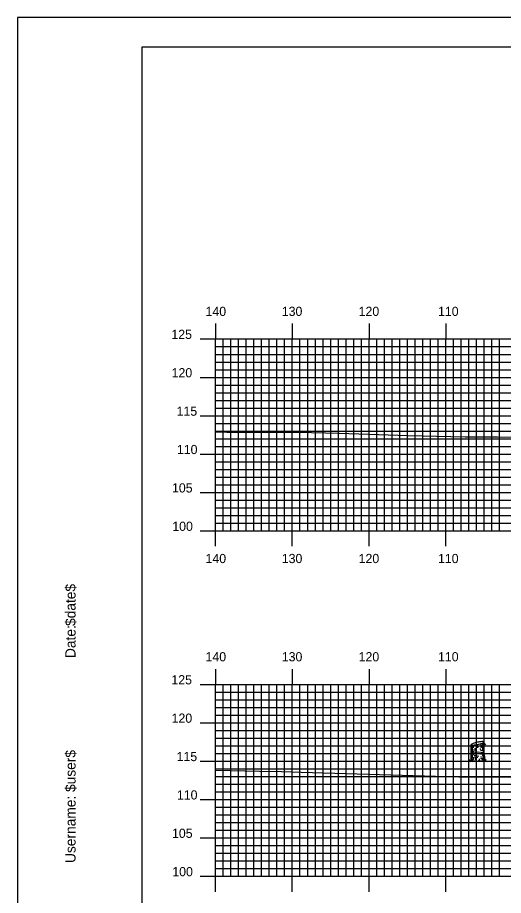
# Model space of a CAD drawing. Extents: x 1772809 to 1773153, y 442591 to 442811.
# Drawn here: x 1772809.3 to 1772872.6, y 442696.2 to 442810.5 of the extents above; entities that cross this region are included whole.
import ezdxf

# ---------------------------------------------------------------- set-up
doc = ezdxf.new("R2010")
doc.units = 0
for name, color, linetype in [('BORDER', 7, 'Continuous'), ('H_V ANNOTATION', 7, 'Continuous'), ('M_Trees_Conifer_Pay', 7, 'Continuous'), ('MAJOR', 7, 'Continuous'), ('MINOR', 7, 'Continuous'), ('PLOT BOUNDARY', 7, 'Continuous'), ('S_Roadway_Centerline', 7, 'Continuous')]:
    doc.layers.add(name, color=color, linetype=linetype)

msp = doc.modelspace()

# ---------------------------------------------------------------- linework, layer by layer
at = {"layer": 'BORDER'}
msp.add_lwpolyline([(1772825.52, 442596.67), (1773145.52, 442596.67), (1773145.52, 442806.67), (1772825.52, 442806.67)], close=True, dxfattribs=at)
at = {"layer": 'M_Trees_Conifer_Pay'}
for p, q in [((1772870.1, 442714.51), (1772870.1, 442716.16)), ((1772868.43, 442714.1), (1772868.43, 442715.82)), ((1772868.48, 442715.78), (1772868.48, 442715.31)), ((1772868.48, 442715.25), (1772868.48, 442714.94)), ((1772868.54, 442715.77), (1772868.54, 442715.68)), ((1772868.54, 442715.6), (1772868.54, 442715.4)), ((1772868.54, 442715.34), (1772868.54, 442715.14)), ((1772868.54, 442715.09), (1772868.54, 442714.76)), ((1772868.66, 442715.77), (1772868.66, 442715.53)), ((1772868.66, 442715.49), (1772868.66, 442715.42)), ((1772868.66, 442715.01), (1772868.66, 442714.88)), ((1772868.88, 442715.79), (1772868.88, 442715.62)), ((1772868.88, 442715.38), (1772868.88, 442715.14)), ((1772869.29, 442715.55), (1772869.29, 442715.46)), ((1772869.68, 442715.83), (1772869.68, 442715.63)), ((1772869.68, 442715.57), (1772869.68, 442715.48)), ((1772869.68, 442715.13), (1772869.68, 442715.03)), ((1772869.91, 442716.02), (1772869.91, 442715.8)), ((1772869.91, 442715.71), (1772869.91, 442715.66)), ((1772869.96, 442715.53), (1772869.91, 442715.47)), ((1772869.91, 442715.33), (1772869.91, 442715.2)), ((1772869.91, 442715.09), (1772869.91, 442714.98)), ((1772870.02, 442716.08), (1772870.02, 442715.92)), ((1772870.02, 442715.85), (1772870.02, 442715.73)), ((1772870.02, 442715.54), (1772870.02, 442715.2)), ((1772870.02, 442715.17), (1772870.02, 442715)), ((1772868.48, 442714.89), (1772868.48, 442714.4)), ((1772868.48, 442714.35), (1772868.48, 442714.1)), ((1772868.54, 442714.7), (1772868.54, 442714.57)), ((1772868.54, 442714.47), (1772868.54, 442714.09)), ((1772868.66, 442714.6), (1772868.66, 442714.46)), ((1772868.66, 442714.2), (1772868.66, 442714.11)), ((1772868.88, 442714.9), (1772868.88, 442714.75)), ((1772868.88, 442714.7), (1772868.88, 442714.53)), ((1772868.88, 442714.25), (1772868.88, 442714.1)), ((1772869.29, 442714.94), (1772869.29, 442714.87)), ((1772869.29, 442714.84), (1772869.29, 442714.69)), ((1772869.29, 442714.4), (1772869.29, 442714.25)), ((1772869.68, 442714.66), (1772869.68, 442714.52)), ((1772869.68, 442714.28), (1772869.68, 442714.2)), ((1772869.91, 442714.84), (1772869.91, 442714.7)), ((1772869.91, 442714.47), (1772869.91, 442714.3)), ((1772870.02, 442714.96), (1772870.02, 442714.74)), ((1772870.02, 442714.71), (1772870.02, 442714.64)), ((1772870.02, 442714.59), (1772870.02, 442714.42)), ((1772868.66, 442713.71), (1772868.83, 442713.77)), ((1772869.1, 442713.64), (1772868.97, 442713.71))]:
    msp.add_line(p, q, dxfattribs=at)
for points in [[(1772868.61, 442715.13), (1772868.61, 442715.22), (1772868.65, 442715.2), (1772868.65, 442715.11)], [(1772869.88, 442715.62), (1772869.85, 442715.53), (1772869.84, 442715.47), (1772869.88, 442715.4)], [(1772869.91, 442715.66), (1772869.95, 442715.58), (1772870, 442715.64), (1772870.05, 442715.71), (1772870.15, 442715.9), (1772870.21, 442715.95), (1772870.24, 442715.95)], [(1772869.93, 442715.4), (1772869.96, 442715.53), (1772870.03, 442715.64), (1772870.06, 442715.71), (1772870.13, 442715.86)], [(1772870.14, 442715.89), (1772870.22, 442715.9), (1772870.29, 442715.8)], [(1772870.1, 442714.51), (1772870.15, 442714.25), (1772870.16, 442713.97), (1772870.22, 442713.85), (1772870.36, 442713.82), (1772870.13, 442713.78), (1772870.13, 442713.78), (1772870.13, 442713.73), (1772870.38, 442713.64), (1772870.11, 442713.66), (1772869.75, 442713.68), (1772869.43, 442713.67), (1772869.44, 442713.75), (1772869.29, 442713.67), (1772869.1, 442713.64), (1772869.12, 442713.58), (1772868.86, 442713.62), (1772868.64, 442713.59), (1772868.34, 442713.61), (1772868.63, 442713.67), (1772868.66, 442713.71), (1772868.5, 442713.76), (1772868.26, 442713.78), (1772868.02, 442713.78), (1772868.36, 442713.83), (1772868.41, 442713.91), (1772868.43, 442714.1)], [(1772868.48, 442714.05), (1772868.46, 442713.97), (1772868.44, 442713.88)], [(1772868.56, 442714.03), (1772868.56, 442713.92), (1772868.51, 442713.83), (1772868.5, 442713.76)], [(1772868.72, 442714.06), (1772868.72, 442713.93), (1772868.63, 442713.83)], [(1772868.95, 442713.82), (1772869.01, 442713.91), (1772869.04, 442714.05)], [(1772869.44, 442713.75), (1772869.51, 442713.89), (1772869.52, 442713.99)], [(1772869.69, 442714.12), (1772869.7, 442713.99), (1772869.77, 442713.95)], [(1772869.75, 442714.73), (1772869.76, 442714.65), (1772869.81, 442714.66), (1772869.8, 442714.83)], [(1772869.96, 442713.73), (1772869.95, 442713.87), (1772869.88, 442714)], [(1772869.92, 442714.22), (1772870, 442714.12), (1772870, 442713.94), (1772870.13, 442713.78)], [(1772870.02, 442714.37), (1772870.03, 442714.22), (1772870.08, 442714.15), (1772870.09, 442713.95)]]:
    msp.add_lwpolyline(points, dxfattribs=at)
for centre, radius, start, end in [((1772870.29, 442711.05), 5.18, 95.3794, 101.7194), ((1772869.88, 442715.41), 0.802, 79.2194, 95.3794), ((1772869.98, 442715.95), 0.251, 71.0501, 79.2194), ((1772870.04, 442716.11), 0.0817, 56.7194, 71.0501), ((1772870.05, 442716.14), 0.0527, 46.923, 56.7194), ((1772870.07, 442716.15), 0.0314, 34.2194, 46.923), ((1772870.07, 442716.16), 0.0226, 11.7194, 23.4074), ((1772870.07, 442716.16), 0.0264, 23.4074, 34.2194), ((1772870.06, 442716.16), 0.0314, 336.5158, 349.2194), ((1772870.07, 442716.16), 0.0264, 349.2194, 0.0315), ((1772870.07, 442716.16), 0.0226, 0.0315, 11.7194), ((1772868.48, 442715.81), 0.0527, 146.7194, 156.5158), ((1772868.46, 442715.82), 0.0314, 156.5158, 169.2194), ((1772868.46, 442715.82), 0.0264, 169.2194, 180.0315), ((1772868.45, 442715.82), 0.0226, 180.0315, 191.7194), ((1772868.45, 442715.82), 0.0226, 191.7194, 203.4074), ((1772868.46, 442715.82), 0.0264, 203.4074, 214.2194), ((1772868.46, 442715.64), 0.0334, 163.9485, 180), ((1772868.46, 442715.64), 0.0334, 180, 196.0515), ((1772868.47, 442715.65), 0.0441, 196.0515, 210), ((1772868.46, 442715.2), 0.0334, 163.9485, 180), ((1772868.46, 442715.2), 0.0334, 180, 196.0515), ((1772868.47, 442715.2), 0.0441, 196.0515, 210), ((1772868.51, 442715.8), 0.0817, 132.3887, 146.7194), ((1772868.46, 442715.83), 0.0314, 214.2194, 226.923), ((1772868.48, 442715.84), 0.0527, 226.923, 236.7194), ((1772868.49, 442715.66), 0.0624, 210, 228.7494), ((1772868.49, 442715.21), 0.0624, 210, 228.7494), ((1772868.62, 442715.67), 0.251, 124.2194, 132.3887), ((1772868.49, 442715.87), 0.0817, 236.7194, 251.0501), ((1772868.56, 442715.74), 0.172, 228.7494, 240), ((1772868.56, 442715.29), 0.172, 228.7494, 240), ((1772868.55, 442716.03), 0.251, 251.0501, 259.2194), ((1772868.93, 442715.22), 0.802, 108.0594, 124.2194), ((1772868.76, 442716.08), 0.571, 240, 240.3367), ((1772868.76, 442715.87), 0.571, 240, 247.0587), ((1772868.76, 442715.64), 0.571, 240, 240.3367), ((1772868.65, 442716.57), 0.802, 259.2194, 275.3794), ((1772868.76, 442716.08), 0.571, 246.8597, 257.9846), ((1772870.29, 442711.05), 5.18, 101.7194, 108.0594), ((1772868.24, 442720.92), 5.18, 275.3794, 281.7194), ((1772869.26, 442719.15), 4.12, 264.081, 266.6676), ((1772869.26, 442719.83), 4.12, 264.6955, 266.7331), ((1772869.26, 442719.6), 4.12, 268.0751, 270), ((1772869.26, 442719.6), 4.12, 270, 270.3581), ((1772868.24, 442720.92), 5.18, 281.7194, 288.0594), ((1772869.26, 442719.39), 4.12, 273.7052, 275.9504), ((1772869.26, 442719.6), 4.12, 275.7849, 277.0558), ((1772869.26, 442719.83), 4.12, 276.238, 278.1032), ((1772869.26, 442719.15), 4.12, 277.6125, 278.1032), ((1772869.76, 442715.64), 0.571, 278.1032, 286.9296), ((1772869.6, 442716.76), 0.802, 288.0594, 304.2194), ((1772869.77, 442716.32), 0.571, 278.1032, 284.3667), ((1772869.77, 442716.47), 0.571, 284.4317, 292.4132), ((1772869.76, 442715.87), 0.571, 284.4493, 297.0429), ((1772869.77, 442716.32), 0.571, 297.0237, 300), ((1772869.76, 442715.64), 0.571, 297.1896, 300), ((1772869.91, 442716.31), 0.251, 304.2194, 312.3887), ((1772869.96, 442716.13), 0.172, 300, 311.2506), ((1772869.96, 442715.97), 0.172, 300, 311.2506), ((1772869.96, 442715.29), 0.172, 300, 311.2506), ((1772870.02, 442716.18), 0.0817, 312.3887, 326.7194), ((1772870.04, 442716.04), 0.0624, 311.2506, 330), ((1772870.04, 442715.89), 0.0624, 311.2506, 330), ((1772870.04, 442715.21), 0.0624, 311.2506, 330), ((1772870.05, 442716.17), 0.0527, 326.7194, 336.5158), ((1772870.06, 442716.03), 0.0334, 343.9485, 354.2151), ((1772870.05, 442716.03), 0.0441, 330, 343.9485), ((1772870.05, 442715.88), 0.0441, 330, 343.9485), ((1772870.06, 442715.88), 0.0334, 343.9485, 354.2151), ((1772870.06, 442715.43), 0.0334, 343.9485, 354.2151), ((1772870.05, 442715.2), 0.0441, 330, 343.9485), ((1772870.06, 442715.2), 0.0334, 343.9485, 354.2151), ((1772868.46, 442714.99), 0.0334, 163.9485, 180), ((1772868.46, 442714.99), 0.0334, 180, 196.0515), ((1772868.47, 442714.99), 0.0441, 196.0515, 210), ((1772868.46, 442714.75), 0.0334, 163.9485, 180), ((1772868.46, 442714.75), 0.0334, 180, 196.0515), ((1772868.47, 442714.75), 0.0441, 196.0515, 210), ((1772868.46, 442714.55), 0.0334, 163.9485, 180), ((1772868.46, 442714.36), 0.0334, 163.9485, 180), ((1772868.46, 442714.36), 0.0334, 180, 196.0515), ((1772868.47, 442714.36), 0.0441, 196.0515, 210), ((1772868.46, 442714.14), 0.0334, 163.9485, 180), ((1772868.46, 442714.14), 0.0334, 180, 196.0515), ((1772868.47, 442714.14), 0.0441, 196.0515, 210), ((1772868.49, 442715), 0.0624, 210, 228.7494), ((1772868.49, 442714.76), 0.0624, 210, 228.7494), ((1772868.49, 442714.37), 0.0624, 210, 228.7494), ((1772868.49, 442714.15), 0.0624, 210, 228.7494), ((1772868.56, 442715.08), 0.172, 228.7494, 240), ((1772868.56, 442714.84), 0.172, 228.7494, 240), ((1772868.56, 442714.45), 0.172, 228.7494, 240), ((1772868.56, 442714.23), 0.172, 228.7494, 240), ((1772868.76, 442715.43), 0.571, 240, 246.8597), ((1772868.76, 442715.19), 0.571, 240, 246.8597), ((1772868.75, 442715), 0.571, 241.2369, 248.0268), ((1772868.76, 442714.8), 0.571, 240, 246.8597), ((1772868.76, 442714.58), 0.571, 240, 244.5314), ((1772868.76, 442715.43), 0.571, 259.2707, 261.8968), ((1772869.26, 442718.94), 4.12, 261.8968, 263.1474), ((1772869.26, 442718.09), 4.12, 262.4438, 263.512), ((1772869.26, 442718.51), 4.12, 263.4991, 265.8397), ((1772869.26, 442718.71), 4.12, 264.716, 266.3193), ((1772869.26, 442718.31), 4.12, 267.8117, 270), ((1772869.26, 442718.94), 4.12, 270, 270.3581), ((1772869.26, 442718.31), 4.12, 270, 270.1328), ((1772869.26, 442718.94), 4.12, 273.1493, 275.4569), ((1772869.26, 442718.31), 4.12, 275.7849, 276.7896), ((1772869.26, 442718.09), 4.12, 277.3684, 278.1032), ((1772869.76, 442714.58), 0.571, 278.1032, 281.637), ((1772869.76, 442715.19), 0.571, 285.3983, 297.1896), ((1772869.76, 442714.8), 0.571, 288.5067, 297.2721), ((1772869.76, 442714.99), 0.571, 289.2907, 300), ((1772869.76, 442715.43), 0.571, 297.1896, 300), ((1772869.96, 442715.08), 0.172, 300, 311.2506), ((1772869.96, 442714.65), 0.172, 300, 311.2506), ((1772869.96, 442714.23), 0.172, 300, 311.2506), ((1772870.04, 442715), 0.0624, 311.2506, 330), ((1772870.04, 442714.56), 0.0624, 311.2506, 330), ((1772870.04, 442714.15), 0.0624, 311.2506, 330), ((1772870.05, 442714.99), 0.0441, 330, 343.9485), ((1772870.06, 442714.99), 0.0334, 343.9485, 354.2151), ((1772870.06, 442714.55), 0.0334, 343.9485, 354.2151), ((1772870.05, 442714.56), 0.0441, 330, 343.9485), ((1772870.05, 442714.14), 0.0441, 330, 343.9485), ((1772870.06, 442714.14), 0.0334, 343.9485, 354.2151)]:
    msp.add_arc(centre, radius, start, end, dxfattribs=at)
at = {"layer": 'MAJOR'}
for p, q in [((1772835.12, 442770.67), (1772835.12, 442768.67)), ((1772845.12, 442770.67), (1772845.12, 442768.67)), ((1772855.12, 442770.67), (1772855.12, 442768.67)), ((1772865.12, 442770.67), (1772865.12, 442768.67)), ((1772833.12, 442768.67), (1772835.12, 442768.67)), ((1772835.12, 442768.67), (1773115.12, 442768.67)), ((1772835.12, 442743.67), (1772835.12, 442768.67)), ((1772835.12, 442743.67), (1772835.12, 442768.67)), ((1772835.12, 442768.67), (1773115.12, 442768.67)), ((1772845.12, 442743.67), (1772845.12, 442768.67)), ((1772855.12, 442743.67), (1772855.12, 442768.67)), ((1772865.12, 442743.67), (1772865.12, 442768.67)), ((1772833.12, 442763.67), (1772835.12, 442763.67)), ((1772835.12, 442763.67), (1773115.12, 442763.67)), ((1772833.12, 442758.67), (1772835.12, 442758.67)), ((1772835.12, 442758.67), (1773115.12, 442758.67)), ((1772833.12, 442753.67), (1772835.12, 442753.67)), ((1772835.12, 442753.67), (1773115.12, 442753.67)), ((1772833.12, 442748.67), (1772835.12, 442748.67)), ((1772835.12, 442748.67), (1773115.12, 442748.67)), ((1772833.12, 442743.67), (1772835.12, 442743.67)), ((1772835.12, 442743.67), (1773115.12, 442743.67)), ((1772835.12, 442743.67), (1773115.12, 442743.67)), ((1772835.12, 442741.66), (1772835.12, 442743.67)), ((1772845.12, 442741.66), (1772845.12, 442743.67)), ((1772855.12, 442741.66), (1772855.12, 442743.67)), ((1772865.12, 442741.66), (1772865.12, 442743.67)), ((1772835.12, 442725.67), (1772835.12, 442723.67)), ((1772845.12, 442725.67), (1772845.12, 442723.67)), ((1772855.12, 442725.67), (1772855.12, 442723.67)), ((1772865.12, 442725.67), (1772865.12, 442723.67)), ((1772833.12, 442723.67), (1772835.12, 442723.67)), ((1772835.12, 442723.67), (1773115.12, 442723.67)), ((1772835.12, 442698.67), (1772835.12, 442723.67)), ((1772835.12, 442698.67), (1772835.12, 442723.67)), ((1772835.12, 442723.67), (1773115.12, 442723.67)), ((1772845.12, 442698.67), (1772845.12, 442723.67)), ((1772855.12, 442698.67), (1772855.12, 442723.67)), ((1772865.12, 442698.67), (1772865.12, 442723.67)), ((1772833.12, 442718.67), (1772835.12, 442718.67)), ((1772835.12, 442718.67), (1773115.12, 442718.67)), ((1772833.12, 442713.67), (1772835.12, 442713.67)), ((1772835.12, 442713.67), (1773115.12, 442713.67)), ((1772833.12, 442708.67), (1772835.12, 442708.67)), ((1772835.12, 442708.67), (1773115.12, 442708.67)), ((1772833.12, 442703.67), (1772835.12, 442703.67)), ((1772835.12, 442703.67), (1773115.12, 442703.67)), ((1772833.12, 442698.67), (1772835.12, 442698.67)), ((1772835.12, 442698.67), (1773115.12, 442698.67)), ((1772835.12, 442698.67), (1773115.12, 442698.67)), ((1772835.12, 442696.66), (1772835.12, 442698.67)), ((1772845.12, 442696.66), (1772845.12, 442698.67)), ((1772855.12, 442696.66), (1772855.12, 442698.67)), ((1772865.12, 442696.66), (1772865.12, 442698.67))]:
    msp.add_line(p, q, dxfattribs=at)
at = {"layer": 'MINOR'}
for p, q in [((1772835.12, 442767.67), (1773115.12, 442767.67)), ((1772835.12, 442767.67), (1772837.12, 442767.67)), ((1772836.12, 442743.67), (1772836.12, 442768.67)), ((1772837.12, 442743.67), (1772837.12, 442768.67)), ((1772838.12, 442743.67), (1772838.12, 442768.67)), ((1772839.12, 442743.67), (1772839.12, 442768.67)), ((1772840.12, 442743.67), (1772840.12, 442768.67)), ((1772841.12, 442743.67), (1772841.12, 442768.67)), ((1772842.12, 442743.67), (1772842.12, 442768.67)), ((1772843.12, 442743.67), (1772843.12, 442768.67)), ((1772844.12, 442743.67), (1772844.12, 442768.67)), ((1772846.12, 442743.67), (1772846.12, 442768.67)), ((1772847.12, 442743.67), (1772847.12, 442768.67)), ((1772848.12, 442743.67), (1772848.12, 442768.67)), ((1772849.12, 442743.67), (1772849.12, 442768.67)), ((1772850.12, 442743.67), (1772850.12, 442768.67)), ((1772851.12, 442743.67), (1772851.12, 442768.67)), ((1772852.12, 442743.67), (1772852.12, 442768.67)), ((1772853.12, 442743.67), (1772853.12, 442768.67)), ((1772854.12, 442743.67), (1772854.12, 442768.67)), ((1772856.12, 442743.67), (1772856.12, 442768.67)), ((1772857.12, 442743.67), (1772857.12, 442768.67)), ((1772858.12, 442743.67), (1772858.12, 442768.67)), ((1772859.12, 442743.67), (1772859.12, 442768.67)), ((1772860.12, 442743.67), (1772860.12, 442768.67)), ((1772861.12, 442743.67), (1772861.12, 442768.67)), ((1772862.12, 442743.67), (1772862.12, 442768.67)), ((1772863.12, 442743.67), (1772863.12, 442768.67)), ((1772864.12, 442743.67), (1772864.12, 442768.67)), ((1772866.12, 442743.67), (1772866.12, 442768.67)), ((1772867.12, 442743.67), (1772867.12, 442768.67)), ((1772868.12, 442743.67), (1772868.12, 442768.67)), ((1772869.12, 442743.67), (1772869.12, 442768.67)), ((1772870.12, 442743.67), (1772870.12, 442768.67)), ((1772871.12, 442743.67), (1772871.12, 442768.67)), ((1772872.12, 442743.67), (1772872.12, 442768.67)), ((1772835.12, 442766.67), (1773115.12, 442766.67)), ((1772835.12, 442766.67), (1772837.12, 442766.67)), ((1772835.12, 442765.67), (1773115.12, 442765.67)), ((1772835.12, 442765.67), (1772837.12, 442765.67)), ((1772835.12, 442764.67), (1773115.12, 442764.67)), ((1772835.12, 442764.67), (1772837.12, 442764.67)), ((1772835.12, 442762.67), (1773115.12, 442762.67)), ((1772835.12, 442762.67), (1772837.12, 442762.67)), ((1772835.12, 442761.67), (1773115.12, 442761.67)), ((1772835.12, 442761.67), (1772837.12, 442761.67)), ((1772835.12, 442760.67), (1773115.12, 442760.67)), ((1772835.12, 442760.67), (1772837.12, 442760.67)), ((1772835.12, 442759.67), (1773115.12, 442759.67)), ((1772835.12, 442759.67), (1772837.12, 442759.67)), ((1772835.12, 442757.67), (1773115.12, 442757.67)), ((1772835.12, 442757.67), (1772837.12, 442757.67)), ((1772835.12, 442756.67), (1773115.12, 442756.67)), ((1772835.12, 442756.67), (1772837.12, 442756.67)), ((1772835.12, 442755.67), (1773115.12, 442755.67)), ((1772835.12, 442755.67), (1772837.12, 442755.67)), ((1772835.12, 442754.67), (1773115.12, 442754.67)), ((1772835.12, 442754.67), (1772837.12, 442754.67)), ((1772835.12, 442752.67), (1773115.12, 442752.67)), ((1772835.12, 442752.67), (1772837.12, 442752.67)), ((1772835.12, 442751.67), (1773115.12, 442751.67)), ((1772835.12, 442751.67), (1772837.12, 442751.67)), ((1772835.12, 442750.67), (1773115.12, 442750.67)), ((1772835.12, 442750.67), (1772837.12, 442750.67)), ((1772835.12, 442749.67), (1773115.12, 442749.67)), ((1772835.12, 442749.67), (1772837.12, 442749.67)), ((1772835.12, 442747.67), (1773115.12, 442747.67)), ((1772835.12, 442747.67), (1772837.12, 442747.67)), ((1772835.12, 442746.67), (1773115.12, 442746.67)), ((1772835.12, 442746.67), (1772837.12, 442746.67)), ((1772835.12, 442745.67), (1773115.12, 442745.67)), ((1772835.12, 442745.67), (1772837.12, 442745.67)), ((1772835.12, 442744.67), (1773115.12, 442744.67)), ((1772835.12, 442744.67), (1772837.12, 442744.67)), ((1772836.12, 442698.67), (1772836.12, 442723.67)), ((1772837.12, 442698.67), (1772837.12, 442723.67)), ((1772838.12, 442698.67), (1772838.12, 442723.67)), ((1772839.12, 442698.67), (1772839.12, 442723.67)), ((1772840.12, 442698.67), (1772840.12, 442723.67)), ((1772841.12, 442698.67), (1772841.12, 442723.67)), ((1772842.12, 442698.67), (1772842.12, 442723.67)), ((1772843.12, 442698.67), (1772843.12, 442723.67)), ((1772844.12, 442698.67), (1772844.12, 442723.67)), ((1772846.12, 442698.67), (1772846.12, 442723.67)), ((1772847.12, 442698.67), (1772847.12, 442723.67)), ((1772848.12, 442698.67), (1772848.12, 442723.67)), ((1772849.12, 442698.67), (1772849.12, 442723.67)), ((1772850.12, 442698.67), (1772850.12, 442723.67)), ((1772851.12, 442698.67), (1772851.12, 442723.67)), ((1772852.12, 442698.67), (1772852.12, 442723.67)), ((1772853.12, 442698.67), (1772853.12, 442723.67)), ((1772854.12, 442698.67), (1772854.12, 442723.67)), ((1772856.12, 442698.67), (1772856.12, 442723.67)), ((1772857.12, 442698.67), (1772857.12, 442723.67)), ((1772858.12, 442698.67), (1772858.12, 442723.67)), ((1772859.12, 442698.67), (1772859.12, 442723.67)), ((1772860.12, 442698.67), (1772860.12, 442723.67)), ((1772861.12, 442698.67), (1772861.12, 442723.67)), ((1772862.12, 442698.67), (1772862.12, 442723.67)), ((1772863.12, 442698.67), (1772863.12, 442723.67)), ((1772864.12, 442698.67), (1772864.12, 442723.67)), ((1772866.12, 442698.67), (1772866.12, 442723.67)), ((1772867.12, 442698.67), (1772867.12, 442723.67)), ((1772868.12, 442698.67), (1772868.12, 442723.67)), ((1772869.12, 442698.67), (1772869.12, 442723.67)), ((1772870.12, 442698.67), (1772870.12, 442723.67)), ((1772871.12, 442698.67), (1772871.12, 442723.67)), ((1772872.12, 442698.67), (1772872.12, 442723.67)), ((1772835.12, 442722.67), (1773115.12, 442722.67)), ((1772835.12, 442722.67), (1772837.12, 442722.67)), ((1772835.12, 442721.67), (1773115.12, 442721.67)), ((1772835.12, 442721.67), (1772837.12, 442721.67)), ((1772835.12, 442720.67), (1773115.12, 442720.67)), ((1772835.12, 442720.67), (1772837.12, 442720.67)), ((1772835.12, 442719.67), (1773115.12, 442719.67)), ((1772835.12, 442719.67), (1772837.12, 442719.67)), ((1772835.12, 442717.67), (1773115.12, 442717.67)), ((1772835.12, 442717.67), (1772837.12, 442717.67)), ((1772835.12, 442716.67), (1773115.12, 442716.67)), ((1772835.12, 442716.67), (1772837.12, 442716.67)), ((1772835.12, 442715.67), (1773115.12, 442715.67)), ((1772835.12, 442715.67), (1772837.12, 442715.67)), ((1772835.12, 442714.67), (1773115.12, 442714.67)), ((1772835.12, 442714.67), (1772837.12, 442714.67)), ((1772835.12, 442712.67), (1773115.12, 442712.67)), ((1772835.12, 442712.67), (1772837.12, 442712.67)), ((1772835.12, 442711.67), (1773115.12, 442711.67)), ((1772835.12, 442711.67), (1772837.12, 442711.67)), ((1772835.12, 442710.67), (1773115.12, 442710.67)), ((1772835.12, 442710.67), (1772837.12, 442710.67)), ((1772835.12, 442709.67), (1773115.12, 442709.67)), ((1772835.12, 442709.67), (1772837.12, 442709.67)), ((1772835.12, 442707.67), (1773115.12, 442707.67)), ((1772835.12, 442707.67), (1772837.12, 442707.67)), ((1772835.12, 442706.67), (1773115.12, 442706.67)), ((1772835.12, 442706.67), (1772837.12, 442706.67)), ((1772835.12, 442705.67), (1773115.12, 442705.67)), ((1772835.12, 442705.67), (1772837.12, 442705.67)), ((1772835.12, 442704.67), (1773115.12, 442704.67)), ((1772835.12, 442704.67), (1772837.12, 442704.67)), ((1772835.12, 442702.67), (1773115.12, 442702.67)), ((1772835.12, 442702.67), (1772837.12, 442702.67)), ((1772835.12, 442701.67), (1773115.12, 442701.67)), ((1772835.12, 442701.67), (1772837.12, 442701.67)), ((1772835.12, 442700.67), (1773115.12, 442700.67)), ((1772835.12, 442700.67), (1772837.12, 442700.67)), ((1772835.12, 442699.67), (1773115.12, 442699.67)), ((1772835.12, 442699.67), (1772837.12, 442699.67))]:
    msp.add_line(p, q, dxfattribs=at)
at = {"layer": 'PLOT BOUNDARY'}
msp.add_lwpolyline([(1772809.33, 442590.55), (1773149.33, 442590.55), (1773149.33, 442810.55), (1772809.33, 442810.55)], close=True, dxfattribs=at)
at = {"layer": 'S_Roadway_Centerline'}
for points in [[(1772835.12, 442756.56), (1772836.57, 442756.52), (1772845.82, 442756.52), (1772851.23, 442756.4), (1772860.16, 442756.09), (1772867.64, 442755.93), (1772871.84, 442755.92), (1772876.95, 442755.9), (1772884.26, 442755.84), (1772889.97, 442755.61), (1772895, 442755.35), (1772902.09, 442755.16), (1772910.01, 442754.92), (1772918.1, 442754.52), (1772932.13, 442754.44), (1772941.59, 442754.28)], [(1772835.12, 442712.49), (1772840.85, 442712.37), (1772843.73, 442712.33), (1772846.26, 442712.22), (1772865.24, 442711.67), (1772866.83, 442711.63), (1772878.99, 442711.64), (1772888.57, 442711.11), (1772891.65, 442710.96), (1772898.35, 442711.19), (1772908.72, 442710.86), (1772912.83, 442710.88), (1772918.2, 442710.59), (1772925.13, 442710.21), (1772930.63, 442710.21), (1772936.63, 442710.11)]]:
    msp.add_lwpolyline(points, dxfattribs=at)

# ---------------------------------------------------------------- texts
at = {"layer": 'BORDER'}
for s, p in [('$date$', (1772816.89, 442731.28)), ('Date:', (1772816.89, 442727.1)), ('$user$', (1772816.89, 442709.65)), ('Username:', (1772816.89, 442700.4))]:
    msp.add_text(s, height=1.339, rotation=90, dxfattribs=at).set_placement(p)
at = {"layer": 'H_V ANNOTATION'}
for s, p in [('140', (1772833.82, 442771.67)), ('130', (1772843.75, 442771.67)), ('120', (1772853.76, 442771.67)), ('110', (1772864.1, 442771.67)), ('125', (1772829.37, 442768.67)), ('120', (1772829.4, 442763.67)), ('115', (1772830.05, 442758.67)), ('110', (1772830.09, 442753.67)), ('105', (1772829.45, 442748.67)), ('100', (1772829.49, 442743.67)), ('140', (1772833.82, 442739.47)), ('130', (1772843.75, 442739.47)), ('120', (1772853.76, 442739.47)), ('110', (1772864.1, 442739.47)), ('140', (1772833.82, 442726.67)), ('130', (1772843.75, 442726.67)), ('120', (1772853.76, 442726.67)), ('110', (1772864.1, 442726.67)), ('125', (1772829.37, 442723.67)), ('120', (1772829.4, 442718.67)), ('115', (1772830.05, 442713.67)), ('110', (1772830.09, 442708.67)), ('105', (1772829.45, 442703.67)), ('100', (1772829.49, 442698.67))]:
    msp.add_text(s, height=1.2, dxfattribs=at).set_placement(p)
at = {"layer": 'MAJOR'}
for p in [(1772835.11, 442743.67), (1772835.11, 442698.67)]:
    msp.add_text('-', height=0.012, dxfattribs=at).set_placement(p)

doc.saveas('drawing.dxf')
